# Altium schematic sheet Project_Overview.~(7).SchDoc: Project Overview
size A4; Date: Not used; ApprovedBy: Not used; CheckedBy: Not used; Author: Not used; CompanyName: STMicroelectronics; DrawnBy: Not used; Engineer: Not used; Organization: Not used; Address1: Not used; Address2: Not used; Address3: Not used; Address4: Not used; DocumentNumber: 1; Revision: Not used; SheetNumber: 1; SheetTotal: 5
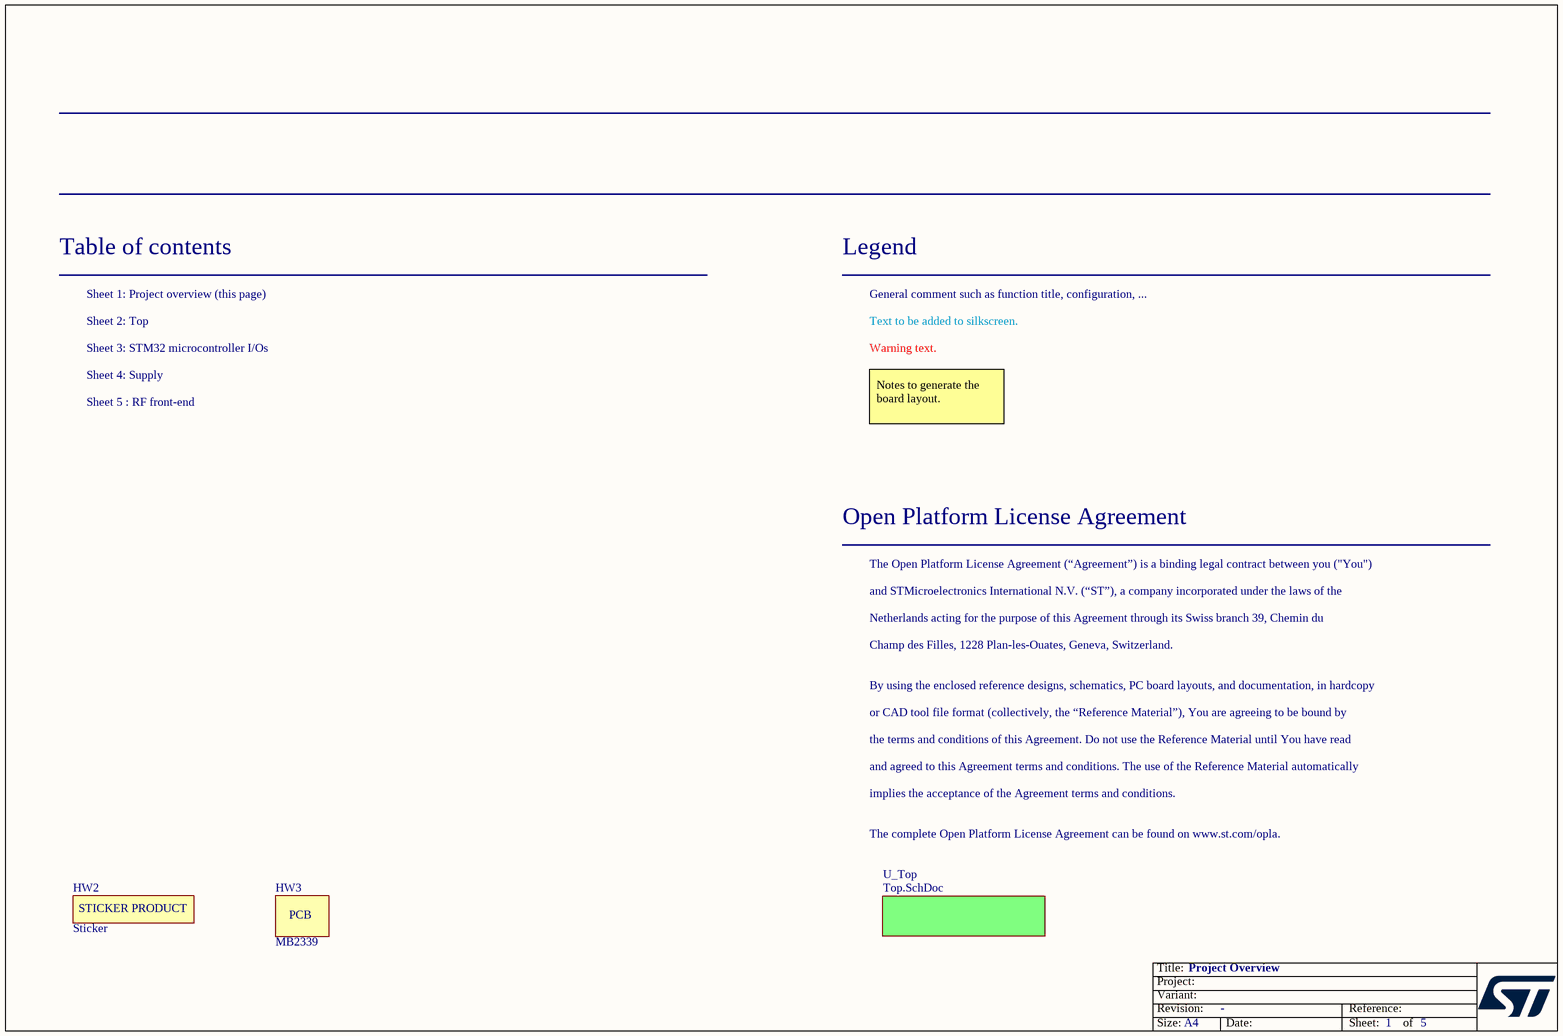
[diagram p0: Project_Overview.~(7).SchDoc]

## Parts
HW2  value Sticker  [STICKER_PRODUCT_25X9]  (hidden comment: STICKER_PRODUCT)  (no BOM)
HW3  value MB2339  (hidden comment: PCB)  (mechanical)

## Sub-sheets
U_Top = Top.SchDoc: no entries

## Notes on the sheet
- Table of contents
- Sheet 1: Project overview (this page)
- Legend
- General comment such as function title, configuration, ...
- Sheet 2: Top
- Sheet 3: STM32 microcontroller I/Os
- Sheet 4: Supply
- Text to be added to silkscreen.
- Warning text.
- Sheet 5 : RF front-end
- Notes to generate the board layout.
- Open Platform License Agreement
- The Open Platform License Agreement (“Agreement”) is a binding legal contract between you ("You")
- and STMicroelectronics International N.V. (“ST”), a company incorporated under the laws of the
- Netherlands acting for the purpose of this Agreement through its Swiss branch 39, Chemin du
- Champ des Filles, 1228 Plan-les-Ouates, Geneva, Switzerland.
- By using the enclosed reference designs, schematics, PC board layouts, and documentation, in hardcopy
- or CAD tool file format (collectively, the “Reference Material”), You are agreeing to be bound by
- the terms and conditions of this Agreement. Do not use the Reference Material until You have read
- and agreed to this Agreement terms and conditions. The use of the Reference Material automatically
- implies the acceptance of the Agreement terms and conditions.
- The complete Open Platform License Agreement can be found on www.st.com/opla.

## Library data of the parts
HW2 = MCD-00547: Sticker product, 25x9mm; Part_Type: Misc; Part_Preference: Recommended; Component_Country_Of_Origin: Unknown; ShowFields: YES; ID: 3197
HW3 = MCD-04477: PCB, MB2339, STM32WL3R Nucleo, 4L2S; Part_Preference: Recommended; Manufacturer: WURTH ELEKTRONIK; Component_Country_Of_Origin: Unknown; ShowFields: YES; ID: 6593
